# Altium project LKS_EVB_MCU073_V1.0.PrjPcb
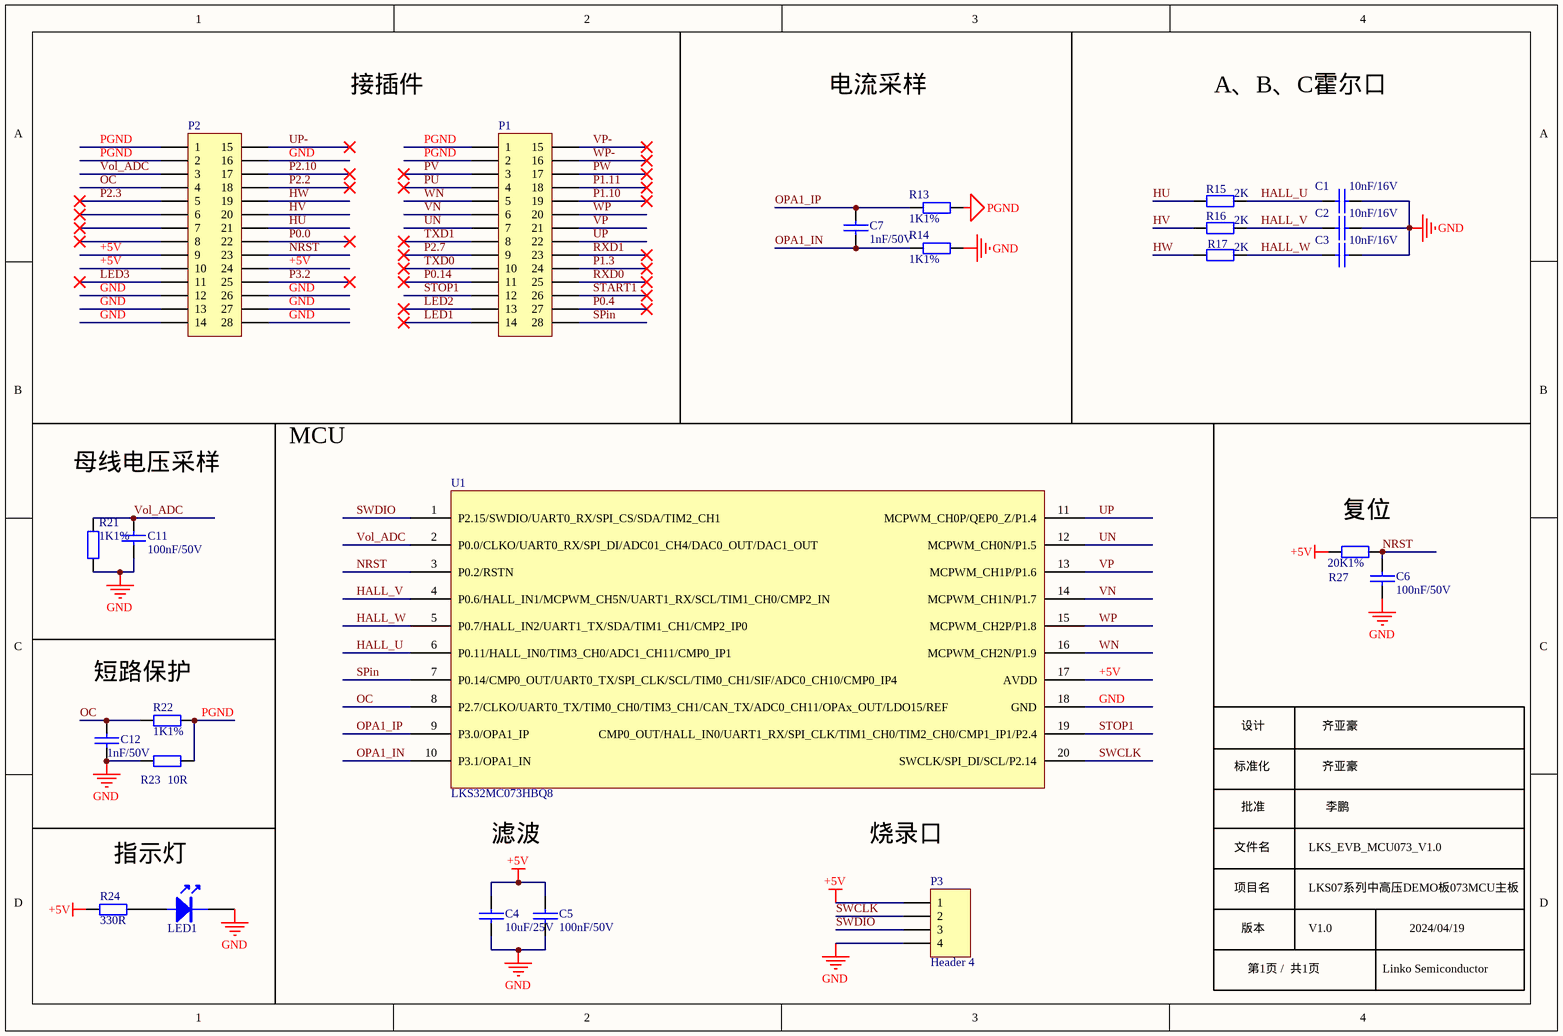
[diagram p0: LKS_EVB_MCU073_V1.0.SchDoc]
1 sheet, 24 parts. Net scope: global (net labels, ports and power ports of the same name join across sheets).
Board file: LKS_EVB_MCU073_V1.0.PcbDoc

## Sheet LKS_EVB_MCU073_V1.0.SchDoc
size A4; SheetNumber: 1; SheetTotal: 1

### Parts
C1  10nF/16V  [0603C]
C2  10nF/16V  [0603C]
C3  10nF/16V  [0603C]
C4  10uF/25V  [0603C]
C5  100nF/50V  [0603C]
C6  100nF/50V  [0603C]
C7  1nF/50V  [0603C]
C11  100nF/50V  [0603C]
C12  1nF/50V  [0603C]
LED1  LED  [LED 0603R]  (value not drawn)
P1  Header 14X2A  [HDR 2X14 底层]  (value not drawn)
P2  Header 14X2A  [HDR 2X14 底层]  (value not drawn)
P3  Header 4  [HDR1X4]
R13  1K1%  [0603R]
R14  1K1%  [0603R]
R15  2K  [0603R]
R16  2K  [0603R]
R17  2K  [0603R]
R21  1K1%  [0603R]
R22  1K1%  [0603R]
R23  10R  [0603R]
R24  330R  [0603R]
R27  20K1%  [0603R]
U1  LKS32MC073HBQ8  [QFN20_3X3]

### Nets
+5V: C4.2 C5.2 P2.9 P2.10 P2.24 P3.1 R24.1 R27.2 U1.17(AVDD)
GND: C1.2 C2.2 C3.2 C4.1 C5.1 C6.2 C11.1 C12.1 LED1.2(K) P2.12 P2.13 P2.14 P2.16 P2.26 P2.27 P2.28 P3.4 R14.1 R21.1 R23.2 U1.18(GND)
PGND: P1.1 P1.2 P2.1 P2.2 R13.1 R22.2 R23.1
HALL_U: C1.1 R15.2 U1.6(P0.11/HALL_IN0/TIM3_CH0/ADC1_CH11/CMP0_IP1)
HALL_V: C2.1 R16.2 U1.4(P0.6/HALL_IN1/MCPWM_CH5N/UART1_RX/SCL/TIM1_CH0/CMP2_IN)
HALL_W: C3.1 R17.2 U1.5(P0.7/HALL_IN2/UART1_TX/SDA/TIM1_CH1/CMP2_IP0)
HU: P2.21 R15.1
HV: P2.20 R16.1
HW: P2.19 R17.1
LED1: P1.14
LED2: P1.13
LED3: P2.11
NRST: C6.1 P2.23 R27.1 U1.3(P0.2/RSTN)
OC: C12.2 P2.4 R22.1 U1.8(P2.7/CLKO/UART0_TX/TIM0_CH0/TIM3_CH1/CAN_TX/ADC0_CH11/OPAx_OUT/LDO15/REF)
OPA1_IN: C7.2 R14.2 U1.10(P3.1/OPA1_IN)
OPA1_IP: C7.1 R13.2 U1.9(P3.0/OPA1_IP)
P0.0: P2.22
P0.4: P1.27
P0.14: P1.11
P1.3: P1.24
P1.10: P1.19
P1.11: P1.18
P2.2: P2.18
P2.3: P2.5
P2.7: P1.9
P2.10: P2.17
P3.2: P2.25
PU: P1.4
PV: P1.3
PW: P1.17
RXD0: P1.25
RXD1: P1.23
SPin: P1.28 U1.7(P0.14/CMP0_OUT/UART0_TX/SPI_CLK/SCL/TIM0_CH1/SIF/ADC0_CH10/CMP0_IP4)
START1: P1.26
STOP1: P1.12 U1.19(CMP0_OUT/HALL_IN0/UART1_RX/SPI_CLK/TIM1_CH0/TIM2_CH0/CMP1_IP1/P2.4)
SWCLK: P3.2 U1.20(SWCLK/SPI_DI/SCL/P2.14)
SWDIO: P3.3 U1.1(P2.15/SWDIO/UART0_RX/SPI_CS/SDA/TIM2_CH1)
TXD0: P1.10
TXD1: P1.8
UN: P1.7 U1.12(MCPWM_CH0N/P1.5)
UP: P1.22 U1.11(MCPWM_CH0P/QEP0_Z/P1.4)
UP-: P2.15
VN: P1.6 U1.14(MCPWM_CH1N/P1.7)
Vol_ADC: C11.2 P2.3 R21.2 U1.2(P0.0/CLKO/UART0_RX/SPI_DI/ADC01_CH4/DAC0_OUT/DAC1_OUT)
VP: P1.21 U1.13(MCPWM_CH1P/P1.6)
VP-: P1.15
WN: P1.5 U1.16(MCPWM_CH2N/P1.9)
WP: P1.20 U1.15(MCPWM_CH2P/P1.8)
WP-: P1.16
NetLED1_1: LED1.1(A) R24.2

Not connected (* = marked no-connect by the designer): P2 6* 7* 8*

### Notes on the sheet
- 接插件
- 母线电压采样
- (near R27) 复位
- 短路保护
- 标准化
- 设计
- 齐亚豪
- 滤波
- 烧录口
- 文件名
- 批准
- LKS_EVB_MCU073_V1.0
- 李鹏
- 指示灯
- 项目名
- LKS07系列中高压DEMO板073MCU主板
- 版本
- 第1页 /  共1页
- V1.0
- Linko Semiconductor
- 2024/04/19
- Labels drawn without touching a wire or pin: A、B、C霍尔口, MCU, 电流采样

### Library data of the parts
C1-C3 = CAP: Capacitor
C4-C7 C11 C12 = C: Capacitor
LED1 = LED: LED_Light
P1 P2 = Header 14X2A: Header, 14-Pin, Dual row
P3 = Header 4: Header, 4-Pin
R13-R17 R21-R24 R27 = Res: Resistor; Value: K
U1 = LKS32MC073HBQ8: 芯片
